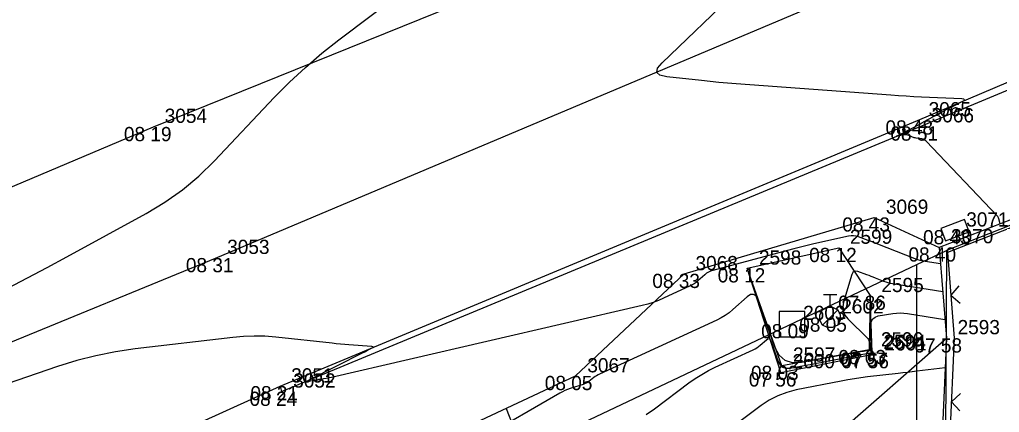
# Model space of a CAD drawing. Extents: x -703403 to -701924, y -1022520 to -1021856.
# Drawn here: x -702379.06 to -702359.77, y -1022295.61 to -1022287.88 of the extents above; entities that cross this region are included whole.
import ezdxf

# ---------------------------------------------------------------- set-up
doc = ezdxf.new("R2010")
doc.units = 0
for name, color, linetype in [('Ex_Major Contours', 7, 'Continuous'), ('Ex_Minor Contours', 7, 'Continuous'), ('Z_betonova_konstrukce', 7, 'Continuous'), ('Z_body', 7, 'Continuous'), ('Z_body_cisla', 7, 'Continuous'), ('Z_body_vysky_redukovane', 7, 'Continuous'), ('Z_hrany_paty', 7, 'Continuous'), ('Z_katastr_hranice', 7, 'Continuous'), ('Z_komunikace', 7, 'Continuous'), ('Z_komunikace_osa', 7, 'Continuous'), ('Z_obruba', 7, 'Continuous'), ('Z_pilire', 7, 'Continuous'), ('Z_ploty', 7, 'Continuous'), ('Z_ploty_znacky', 7, 'Continuous'), ('Z_site_nerozlisene_znaky', 7, 'Continuous'), ('Z_site_vodovod_znaky', 7, 'Continuous'), ('Z_technicke_srafy', 7, 'Continuous')]:
    doc.layers.add(name, color=color, linetype=linetype)

# ---------------------------------------------------------------- blocks, each defined once
blk = doc.blocks.new('POINT_DISPLAY')
blk.add_line((0, 0), (0, 0))
blk = doc.blocks.new('Z18')
for p, q in [((-0.13, 0.45), (0.13, 0.45)), ((0, 0.2), (0, 0.45)), ((-0.15, 0.15), (-0.05, 0.2)), ((-0.05, 0.2), (0.05, 0.2)), ((0.05, 0.2), (0.15, 0.15)), ((-0.2, 0.05), (-0.15, 0.15)), ((-0.2, -0.05), (-0.2, 0.05)), ((0.15, 0.15), (-0.15, -0.15)), ((0.15, 0.15), (0.2, 0.05)), ((0.2, 0.05), (0.2, -0.05)), ((-0.15, -0.15), (-0.2, -0.05)), ((-0.05, -0.2), (-0.15, -0.15)), ((0.15, -0.15), (0.05, -0.2)), ((0.2, -0.05), (0.15, -0.15)), ((0.05, -0.2), (-0.05, -0.2))]:
    blk.add_line(p, q)
blk = doc.blocks.new('Z666')
for p, q in [((-0.25, 0.13), (-0.25, -0.13)), ((0.25, 0.13), (-0.25, 0.13)), ((0.25, -0.13), (0.25, 0.13)), ((-0.25, -0.13), (0.25, -0.13))]:
    blk.add_line(p, q)
blk = doc.blocks.new('Z608')
for p, q in [((0.25, 0.25), (-0.25, 0.25)), ((-0.25, 0.25), (-0.25, -0.25)), ((0.25, -0.25), (0.25, 0.25)), ((-0.25, -0.25), (0.25, -0.25))]:
    blk.add_line(p, q)
blk = doc.blocks.new('Z212')
for p, q in [((-0.17, 0.17), (0, 0)), ((0, 0), (0.17, 0.17))]:
    blk.add_line(p, q)

msp = doc.modelspace()

# ---------------------------------------------------------------- linework, layer by layer
at = {"layer": 'Ex_Major Contours'}
msp.add_lwpolyline([(-702360.882, -1022293.233), (-702361.869, -1022293.078), (-702361.913, -1022293.069), (-702361.956, -1022293.059), (-702361.999, -1022293.046), (-702362.041, -1022293.031), (-702362.207, -1022292.965), (-702362.249, -1022292.948), (-702362.291, -1022292.932), (-702362.333, -1022292.917), (-702362.375, -1022292.901), (-702362.555, -1022292.836), (-702362.596, -1022292.827), (-702362.629, -1022292.834), (-702362.654, -1022292.856), (-702362.671, -1022292.894), (-702362.834, -1022293.436), (-702362.851, -1022293.528), (-702362.842, -1022293.614), (-702362.809, -1022293.694), (-702362.751, -1022293.768), (-702362.36, -1022294.157), (-702362.346, -1022294.175), (-702362.335, -1022294.195), (-702362.329, -1022294.216), (-702362.326, -1022294.239), (-702362.326, -1022294.383), (-702362.325, -1022294.385), (-702362.412, -1022294.402), (-702362.441, -1022294.408), (-702362.47, -1022294.413), (-702363.662, -1022294.628), (-702363.841, -1022294.636), (-702363.987, -1022294.588), (-702364.102, -1022294.485), (-702364.186, -1022294.326), (-702364.524, -1022293.387), (-702364.561, -1022293.317), (-702364.608, -1022293.285), (-702364.664, -1022293.291), (-702364.73, -1022293.335), (-702365.014, -1022293.586), (-702365.087, -1022293.646), (-702365.163, -1022293.7), (-702365.244, -1022293.748), (-702365.328, -1022293.791), (-702367.639, -1022294.856), (-702367.668, -1022294.87), (-702367.696, -1022294.886), (-702367.723, -1022294.903), (-702367.749, -1022294.921), (-702367.852, -1022294.999), (-702367.878, -1022295.017), (-702367.905, -1022295.032), (-702367.934, -1022295.046), (-702367.964, -1022295.057), (-702368.218, -1022295.14), (-702368.27, -1022295.159), (-702368.321, -1022295.18), (-702368.371, -1022295.204), (-702368.419, -1022295.23), (-702369.963, -1022296.123)], dxfattribs=at)
at = {"layer": 'Ex_Minor Contours'}
for points in [[(-702379.292, -1022293.163), (-702378.901, -1022292.961), (-702378.512, -1022292.755), (-702378.126, -1022292.546), (-702376.562, -1022291.691), (-702376.196, -1022291.472), (-702375.851, -1022291.227), (-702375.526, -1022290.956), (-702375.221, -1022290.658), (-702374.043, -1022289.413), (-702373.743, -1022289.108), (-702373.431, -1022288.817), (-702373.107, -1022288.539), (-702372.77, -1022288.274), (-702366.514, -1022283.556), (-702366.419, -1022283.464), (-702366.361, -1022283.359), (-702366.339, -1022283.24), (-702366.355, -1022283.109), (-702366.558, -1022282.281)], [(-702359.754, -1022291.898), (-702359.779, -1022291.797), (-702359.784, -1022291.781), (-702359.791, -1022291.765), (-702359.8, -1022291.751), (-702359.81, -1022291.738), (-702361.209, -1022290.271), (-702361.227, -1022290.255), (-702361.247, -1022290.242), (-702361.27, -1022290.233), (-702361.293, -1022290.227), (-702361.403, -1022290.21), (-702361.423, -1022290.206), (-702361.442, -1022290.201), (-702361.46, -1022290.195), (-702361.479, -1022290.188), (-702361.551, -1022290.157), (-702361.57, -1022290.15), (-702361.588, -1022290.147), (-702361.607, -1022290.145), (-702361.627, -1022290.147), (-702361.783, -1022290.171), (-702361.788, -1022290.172), (-702361.79, -1022290.171), (-702361.788, -1022290.17), (-702361.784, -1022290.168), (-702361.75, -1022290.15), (-702361.739, -1022290.144), (-702361.448, -1022289.993), (-702361.397, -1022289.966), (-702361.347, -1022289.939), (-702361.297, -1022289.912), (-702361.247, -1022289.885), (-702360.882, -1022289.684), (-702360.835, -1022289.658), (-702360.787, -1022289.633), (-702360.739, -1022289.609), (-702360.691, -1022289.585), (-702360.497, -1022289.491), (-702360.461, -1022289.47), (-702360.451, -1022289.455), (-702360.467, -1022289.444), (-702360.508, -1022289.439), (-702361.303, -1022289.402), (-702361.453, -1022289.394), (-702361.604, -1022289.385), (-702361.754, -1022289.376), (-702361.904, -1022289.365), (-702364.949, -1022289.14), (-702365.12, -1022289.126), (-702365.291, -1022289.112), (-702365.462, -1022289.095), (-702365.632, -1022289.078), (-702366.315, -1022289.004), (-702366.449, -1022288.973), (-702366.51, -1022288.917), (-702366.496, -1022288.835), (-702366.409, -1022288.729), (-702363.477, -1022285.912)], [(-702360.924, -1022292.687), (-702361.227, -1022292.64), (-702361.277, -1022292.63), (-702361.326, -1022292.618), (-702361.375, -1022292.604), (-702361.423, -1022292.586), (-702362.161, -1022292.294), (-702362.208, -1022292.275), (-702362.256, -1022292.257), (-702362.303, -1022292.239), (-702362.351, -1022292.222), (-702362.541, -1022292.153), (-702362.589, -1022292.139), (-702362.637, -1022292.133), (-702362.686, -1022292.133), (-702362.735, -1022292.14), (-702363.42, -1022292.293), (-702363.551, -1022292.322), (-702363.681, -1022292.353), (-702363.811, -1022292.386), (-702363.94, -1022292.42), (-702365.409, -1022292.814), (-702365.452, -1022292.829), (-702365.493, -1022292.847), (-702365.531, -1022292.871), (-702365.566, -1022292.899), (-702365.704, -1022293.021), (-702365.739, -1022293.05), (-702365.776, -1022293.076), (-702365.815, -1022293.099), (-702365.856, -1022293.12), (-702366.379, -1022293.361), (-702366.481, -1022293.405), (-702366.585, -1022293.444), (-702366.691, -1022293.477), (-702366.798, -1022293.504), (-702372.916, -1022294.919), (-702372.968, -1022294.93), (-702373.019, -1022294.94), (-702373.071, -1022294.95), (-702373.123, -1022294.958), (-702373.331, -1022294.991), (-702373.37, -1022294.995), (-702373.385, -1022294.991), (-702373.375, -1022294.979), (-702373.341, -1022294.959), (-702372.295, -1022294.431), (-702372.273, -1022294.42), (-702372.25, -1022294.409), (-702372.228, -1022294.397), (-702372.205, -1022294.385), (-702372.116, -1022294.339), (-702372.099, -1022294.328), (-702372.095, -1022294.32), (-702372.102, -1022294.315), (-702372.121, -1022294.311), (-702372.572, -1022294.278), (-702372.655, -1022294.272), (-702372.738, -1022294.264), (-702372.822, -1022294.256), (-702372.905, -1022294.248), (-702374.013, -1022294.128), (-702374.226, -1022294.111), (-702374.438, -1022294.106), (-702374.65, -1022294.113), (-702374.862, -1022294.132), (-702376.782, -1022294.359), (-702377.17, -1022294.415), (-702377.554, -1022294.492), (-702377.933, -1022294.589), (-702378.308, -1022294.707), (-702385.656, -1022297.232)], [(-702366.718, -1022295.65), (-702366.56, -1022295.541), (-702365.878, -1022295.029), (-702365.755, -1022294.941), (-702365.628, -1022294.861), (-702365.497, -1022294.787), (-702365.362, -1022294.721), (-702364.613, -1022294.376), (-702364.577, -1022294.357), (-702364.542, -1022294.336), (-702364.509, -1022294.313), (-702364.478, -1022294.287), (-702364.355, -1022294.179), (-702364.327, -1022294.16), (-702364.302, -1022294.157), (-702364.282, -1022294.171), (-702364.266, -1022294.201), (-702364.12, -1022294.607), (-702364.084, -1022294.675), (-702364.034, -1022294.72), (-702363.971, -1022294.74), (-702363.894, -1022294.737), (-702363.54, -1022294.673), (-702363.454, -1022294.658), (-702363.367, -1022294.641), (-702363.28, -1022294.625), (-702363.193, -1022294.608), (-702362.287, -1022294.429), (-702362.285, -1022294.428), (-702362.284, -1022294.427), (-702362.284, -1022294.425), (-702362.285, -1022294.423), (-702362.291, -1022294.415), (-702362.293, -1022294.41), (-702362.293, -1022294.405), (-702362.295, -1022293.88), (-702362.286, -1022293.815), (-702362.259, -1022293.765), (-702362.214, -1022293.731), (-702362.151, -1022293.711), (-702361.864, -1022293.664), (-702361.792, -1022293.655), (-702361.721, -1022293.652), (-702361.649, -1022293.654), (-702361.577, -1022293.663), (-702360.839, -1022293.779)], [(-702360.835, -1022294.733), (-702361.392, -1022294.799), (-702361.484, -1022294.81), (-702361.577, -1022294.821), (-702361.67, -1022294.831), (-702361.763, -1022294.842), (-702362.362, -1022294.91), (-702362.492, -1022294.926), (-702362.622, -1022294.945), (-702362.752, -1022294.967), (-702362.881, -1022294.991), (-702363.767, -1022295.166), (-702363.953, -1022295.214), (-702364.13, -1022295.281), (-702364.299, -1022295.368), (-702364.459, -1022295.475), (-702365.412, -1022296.191)]]:
    msp.add_lwpolyline(points, dxfattribs=at)
at = {"layer": 'Z_betonova_konstrukce'}
for p, q in [((-702364.73, -1022292.77), (-702362.93, -1022292.37)), ((-702362.93, -1022292.37), (-702362.31, -1022293.31)), ((-702364.05, -1022294.69), (-702364.73, -1022292.77)), ((-702364.07, -1022294.82), (-702364.73, -1022292.77)), ((-702362.31, -1022293.31), (-702362.33, -1022294.38)), ((-702362.27, -1022294.43), (-702362.31, -1022293.31)), ((-702364.07, -1022294.82), (-702362.25, -1022294.46)), ((-702362.33, -1022294.38), (-702364.05, -1022294.69))]:
    msp.add_line(p, q, dxfattribs=at)
at = {"layer": 'Z_hrany_paty'}
for p, q in [((-702365.97, -1022292.88), (-702362.23, -1022291.77)), ((-702362.23, -1022291.77), (-702360.95, -1022292.36)), ((-702368.11, -1022294.89), (-702365.97, -1022292.88)), ((-702364.55, -1022297.42), (-702360.81, -1022294.15)), ((-702374.61, -1022297.92), (-702368.11, -1022294.89))]:
    msp.add_line(p, q, dxfattribs=at)
at = {"layer": 'Z_katastr_hranice'}
for p, q in [((-702358.05, -1022291.34), (-702360.81, -1022292.42)), ((-702361.39, -1022292.7), (-702360.81, -1022292.42)), ((-702360.81, -1022292.42), (-702360.86, -1022304.48)), ((-702423.94, -1022322.29), (-702361.39, -1022292.7)), ((-702361.4, -1022304.51), (-702361.39, -1022292.7))]:
    msp.add_line(p, q, dxfattribs=at)
at = {"layer": 'Z_komunikace'}
for p, q in [((-702376.42, -1022289.99), (-702363.57, -1022284.79)), ((-702361.38, -1022289.86), (-702356.97, -1022287.99)), ((-702373.93, -1022295.09), (-702361.38, -1022289.86)), ((-702385.06, -1022293.63), (-702376.42, -1022289.99)), ((-702384.26, -1022299.78), (-702373.93, -1022295.09))]:
    msp.add_line(p, q, dxfattribs=at)
at = {"layer": 'Z_komunikace_osa'}
for p, q in [((-702375.2, -1022292.57), (-702362.61, -1022287.26)), ((-702385.9, -1022296.96), (-702375.2, -1022292.57))]:
    msp.add_line(p, q, dxfattribs=at)
at = {"layer": 'Z_obruba'}
for p, q in [((-702361.33, -1022289.98), (-702356.94, -1022288.15)), ((-702373.9, -1022295.2), (-702361.33, -1022289.98)), ((-702373.93, -1022295.09), (-702373.9, -1022295.2))]:
    msp.add_line(p, q, dxfattribs=at)
at = {"layer": 'Z_ploty'}
for p, q in [((-702358.08, -1022291.25), (-702360.95, -1022292.36)), ((-702358.03, -1022291.39), (-702360.79, -1022292.46)), ((-702360.95, -1022292.36), (-702360.81, -1022294.15)), ((-702360.79, -1022292.46), (-702360.66, -1022294.15)), ((-702360.81, -1022294.15), (-702360.99, -1022298.38)), ((-702360.66, -1022294.15), (-702360.84, -1022298.39))]:
    msp.add_line(p, q, dxfattribs=at)
at = {"layer": 'Z_technicke_srafy'}
msp.add_line((-702369.48, -1022295.53), (-702368.26, -1022298.64), dxfattribs=at)

# ---------------------------------------------------------------- block references
at = {"layer": 'Z_body'}
for p in [(-702361.38, -1022289.86), (-702376.42, -1022289.99), (-702361.33, -1022289.98), (-702362.23, -1022291.77), (-702360.64, -1022292.02), (-702362.93, -1022292.37), (-702360.95, -1022292.36), (-702375.2, -1022292.57), (-702364.73, -1022292.77), (-702365.97, -1022292.88), (-702362.31, -1022293.31), (-702363.1, -1022293.74), (-702363.85, -1022293.87), (-702360.81, -1022294.15), (-702362.33, -1022294.38), (-702362.27, -1022294.43), (-702362.25, -1022294.46), (-702364.05, -1022294.69), (-702368.11, -1022294.89), (-702364.07, -1022294.82), (-702373.93, -1022295.09), (-702373.9, -1022295.2)]:
    msp.add_blockref('POINT_DISPLAY', p, dxfattribs=at)
at = {"layer": 'Z_pilire', "rotation": 20.7}
msp.add_blockref('Z666', (-702360.64, -1022292.02), dxfattribs=at)
at = {"layer": 'Z_ploty_znacky'}
for p, rotation in [((-702360.72, -1022293.3), -85.49999999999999), ((-702360.71, -1022295.4), -92.39999999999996)]:
    msp.add_blockref('Z212', p, dxfattribs=dict(at, rotation=rotation))
at = {"layer": 'Z_site_nerozlisene_znaky'}
msp.add_blockref('Z608', (-702363.85, -1022293.87), dxfattribs=at)
at = {"layer": 'Z_site_vodovod_znaky'}
msp.add_blockref('Z18', (-702363.1, -1022293.74), dxfattribs=at)

# ---------------------------------------------------------------- texts
at = {"layer": 'Z_body_cisla'}
for s, p in [('3065', (-702361.16, -1022289.78)), ('3054', (-702376.2, -1022289.91)), ('3066', (-702361.1, -1022289.9)), ('3069', (-702362, -1022291.7)), ('3071', (-702360.42, -1022291.95)), ('2599', (-702362.71, -1022292.29)), ('3070', (-702360.72, -1022292.28)), ('3053', (-702374.97, -1022292.49)), ('2598', (-702364.5, -1022292.7)), ('3068', (-702365.75, -1022292.81)), ('2595', (-702362.09, -1022293.24)), ('2602', (-702362.88, -1022293.66)), ('2603', (-702363.63, -1022293.79)), ('2593', (-702360.59, -1022294.07)), ('2596', (-702362.1, -1022294.31)), ('2594', (-702362.05, -1022294.36)), ('2601', (-702362.03, -1022294.39)), ('2597', (-702363.83, -1022294.61)), ('3067', (-702367.88, -1022294.82)), ('2600', (-702363.84, -1022294.74)), ('3051', (-702373.71, -1022295.02)), ('3052', (-702373.67, -1022295.12))]:
    msp.add_text(s, height=0.28, dxfattribs=at).set_placement(p)
at = {"layer": 'Z_body_vysky_redukovane'}
for s, p in [('08 48', (-702362.01, -1022290.14)), ('08 19', (-702377.003, -1022290.27)), ('08 51', (-702361.913, -1022290.26)), ('08 43', (-702362.86, -1022292.05)), ('08 43', (-702361.27, -1022292.3)), ('08 12', (-702363.513, -1022292.65)), ('08 40', (-702361.557, -1022292.64)), ('08 31', (-702375.783, -1022292.85)), ('08 12', (-702365.313, -1022293.05)), ('08 33', (-702366.6, -1022293.16)), ('07 86', (-702362.94, -1022293.59)), ('08 05', (-702363.707, -1022294.02)), ('08 09', (-702364.457, -1022294.15)), ('07 58', (-702361.44, -1022294.43)), ('08 03', (-702362.937, -1022294.66)), ('07 57', (-702362.9, -1022294.71)), ('07 56', (-702362.88, -1022294.74)), ('08 03', (-702364.657, -1022294.97)), ('08 05', (-702368.717, -1022295.17)), ('07 56', (-702364.7, -1022295.1)), ('08 21', (-702374.513, -1022295.37)), ('08 24', (-702374.53, -1022295.48))]:
    msp.add_text(s, height=0.28, dxfattribs=at).set_placement(p)

doc.saveas('drawing.dxf')
